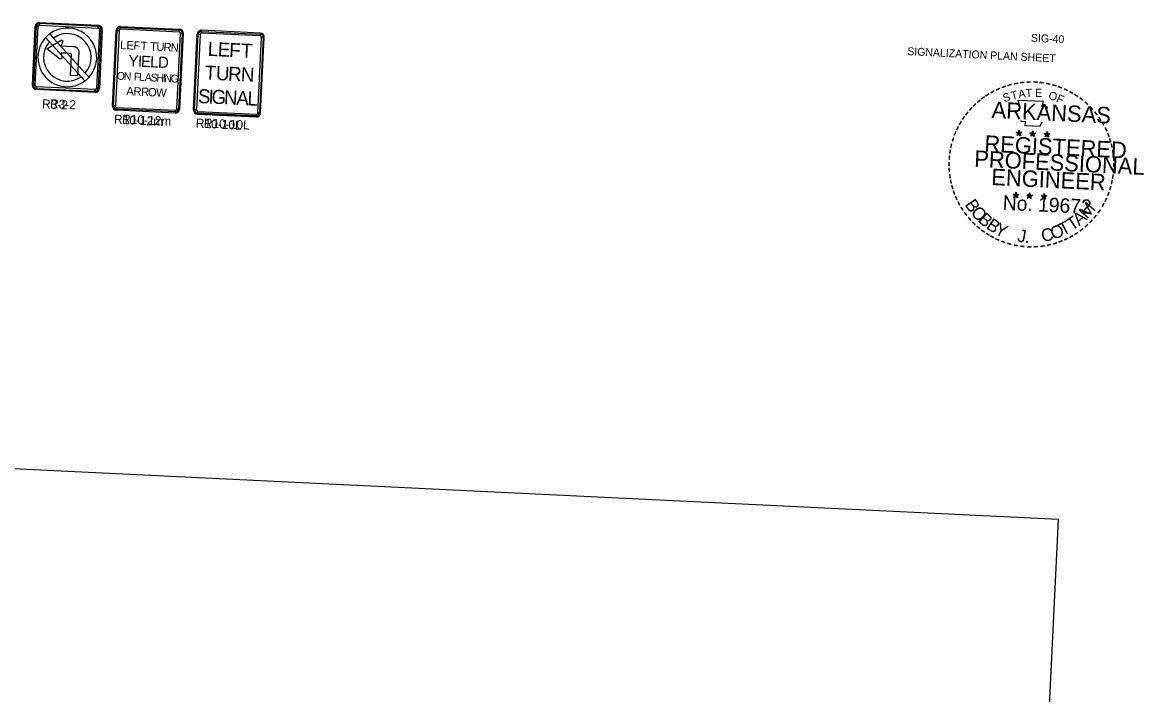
# Model space of a CAD drawing. Extents: x 662220 to 671027, y 641390 to 743815.
# Drawn here: x 662687 to 663189, y 642399 to 642699 of the extents above; entities that cross this region are included whole.
import ezdxf

# ---------------------------------------------------------------- set-up
doc = ezdxf.new("R2010")
doc.units = 0
for name, color, linetype in [('Default', 7, 'Continuous'), ('R_Border', 7, 'Continuous'), ('R_Proposed Road Annot', 7, 'Continuous'), ('TE_SG black legend_z_n', 7, 'Continuous'), ('TE_SG red shield_z_n', 7, 'Continuous'), ('TE_SG sign edge_z_n', 7, 'Continuous')]:
    doc.layers.add(name, color=color, linetype=linetype)

msp = doc.modelspace()

# ---------------------------------------------------------------- linework, layer by layer
at = {"layer": 'R_Border'}
for p, q in [((663131.65, 642650.37), (663132.9, 642649.9)), ((663131.65, 642650.37), (663132.56, 642650.16)), ((663131.65, 642650.37), (663132.49, 642649.88)), ((663132.06, 642648.86), (663132.9, 642649.9)), ((663132.06, 642648.86), (663132.56, 642649.73)), ((663132.97, 642651.24), (663132.77, 642650.32)), ((663132.9, 642649.9), (663132.97, 642651.24)), ((663134.19, 642650.25), (663132.9, 642649.9)), ((663133.63, 642648.78), (663132.9, 642649.9)), ((663132.97, 642651.24), (663133.1, 642650.32)), ((663134.19, 642650.25), (663133.14, 642650.12)), ((663133.63, 642648.78), (663133.18, 642649.87)), ((663134.19, 642650.25), (663133.43, 642649.91)), ((663137.76, 642650.08), (663139.01, 642649.61)), ((663137.76, 642650.08), (663138.67, 642649.87)), ((663137.76, 642650.08), (663138.6, 642649.59)), ((663139.08, 642650.94), (663138.88, 642650.03)), ((663139.01, 642649.61), (663139.08, 642650.94)), ((663140.3, 642649.95), (663139.01, 642649.61)), ((663139.08, 642650.94), (663139.21, 642650.02)), ((663140.3, 642649.95), (663139.25, 642649.82)), ((663140.3, 642649.95), (663139.54, 642649.61)), ((663144.21, 642649.72), (663145.46, 642649.25)), ((663144.21, 642649.72), (663145.12, 642649.51)), ((663144.21, 642649.72), (663145.05, 642649.23)), ((663145.53, 642650.59), (663145.33, 642649.67)), ((663145.46, 642649.25), (663145.53, 642650.59)), ((663145.53, 642650.59), (663145.66, 642649.66)), ((663132.06, 642648.86), (663132.88, 642649.61)), ((663133.63, 642648.78), (663132.88, 642649.6)), ((663138.17, 642648.56), (663139.01, 642649.61)), ((663138.17, 642648.56), (663138.67, 642649.43)), ((663138.17, 642648.56), (663138.99, 642649.32)), ((663139.74, 642648.48), (663138.99, 642649.3)), ((663139.74, 642648.48), (663139.01, 642649.61)), ((663139.74, 642648.48), (663139.29, 642649.57)), ((663144.62, 642648.2), (663145.46, 642649.25)), ((663144.62, 642648.2), (663145.12, 642649.07)), ((663144.62, 642648.2), (663145.44, 642648.96)), ((663146.19, 642648.13), (663145.44, 642648.95)), ((663146.75, 642649.59), (663145.46, 642649.25)), ((663146.19, 642648.13), (663145.46, 642649.25)), ((663146.75, 642649.59), (663145.7, 642649.47)), ((663146.19, 642648.13), (663145.74, 642649.21)), ((663146.75, 642649.59), (663145.99, 642649.26)), ((663130.29, 642622.67), (663131.54, 642622.2)), ((663130.29, 642622.67), (663131.2, 642622.46)), ((663130.29, 642622.67), (663131.13, 642622.18)), ((663130.7, 642621.15), (663131.54, 642622.2)), ((663130.7, 642621.15), (663131.2, 642622.02)), ((663130.7, 642621.15), (663131.52, 642621.91)), ((663131.61, 642623.54), (663131.41, 642622.62)), ((663132.27, 642621.08), (663131.52, 642621.9)), ((663131.54, 642622.2), (663131.61, 642623.54)), ((663132.83, 642622.55), (663131.54, 642622.2)), ((663132.27, 642621.08), (663131.54, 642622.2)), ((663131.61, 642623.54), (663131.74, 642622.61)), ((663132.83, 642622.55), (663131.78, 642622.42)), ((663132.27, 642621.08), (663131.82, 642622.17)), ((663132.83, 642622.55), (663132.07, 642622.21)), ((663136.39, 642622.37), (663137.65, 642621.91)), ((663136.39, 642622.37), (663137.31, 642622.16)), ((663136.39, 642622.37), (663137.24, 642621.89)), ((663136.8, 642620.86), (663137.65, 642621.91)), ((663136.8, 642620.86), (663137.31, 642621.73)), ((663136.8, 642620.86), (663137.63, 642621.61)), ((663137.71, 642623.24), (663137.52, 642622.33)), ((663138.37, 642620.78), (663137.63, 642621.6)), ((663137.65, 642621.91), (663137.71, 642623.24)), ((663138.94, 642622.25), (663137.65, 642621.91)), ((663138.37, 642620.78), (663137.65, 642621.91)), ((663137.71, 642623.24), (663137.85, 642622.32)), ((663138.94, 642622.25), (663137.88, 642622.12)), ((663138.37, 642620.78), (663137.92, 642621.87)), ((663138.94, 642622.25), (663138.17, 642621.91)), ((663142.85, 642622.02), (663144.11, 642621.55)), ((663142.85, 642622.02), (663143.77, 642621.81)), ((663142.85, 642622.02), (663143.7, 642621.53)), ((663143.27, 642620.51), (663144.11, 642621.55)), ((663143.27, 642620.51), (663143.77, 642621.38)), ((663143.27, 642620.51), (663144.09, 642621.26)), ((663144.17, 642622.89), (663143.98, 642621.98)), ((663144.84, 642620.43), (663144.09, 642621.25)), ((663144.11, 642621.55), (663144.17, 642622.89)), ((663145.4, 642621.9), (663144.11, 642621.55)), ((663144.84, 642620.43), (663144.11, 642621.55)), ((663144.17, 642622.89), (663144.31, 642621.97)), ((663145.4, 642621.9), (663144.34, 642621.77)), ((663144.84, 642620.43), (663144.39, 642621.52)), ((663145.4, 642621.9), (663144.63, 642621.56))]:
    msp.add_line(p, q, dxfattribs=at)
for points in [[(663132.49, 642664.55), (663133.32, 642661.48)], [(663145.17, 642660.55), (663145.74, 642661.57), (663143.23, 642661.6), (663143.88, 642664), (663132.49, 642664.55)], [(663133.85, 642655.6), (663133.84, 642655.28), (663135.9, 642655.11), (663135.61, 642653.39), (663142.45, 642653.06), (663143.28, 642654.98)], [(663132.97, 642651.24), (663133.63, 642648.78), (663131.65, 642650.37), (663134.19, 642650.25), (663132.06, 642648.86), (663132.97, 642651.24)], [(663139.08, 642650.94), (663139.74, 642648.48), (663137.76, 642650.08), (663140.3, 642649.95), (663138.17, 642648.56), (663139.08, 642650.94)], [(663145.53, 642650.59), (663146.19, 642648.13), (663144.21, 642649.72), (663146.75, 642649.59), (663144.62, 642648.2), (663145.53, 642650.59)], [(663131.61, 642623.54), (663132.27, 642621.08), (663130.29, 642622.67), (663132.83, 642622.55), (663130.7, 642621.15), (663131.61, 642623.54)], [(663137.71, 642623.24), (663138.37, 642620.78), (663136.39, 642622.37), (663138.94, 642622.25), (663136.8, 642620.86), (663137.71, 642623.24)], [(663144.17, 642622.89), (663144.84, 642620.43), (663142.85, 642622.02), (663145.4, 642621.9), (663143.27, 642620.51), (663144.17, 642622.89)]]:
    msp.add_lwpolyline(points, dxfattribs=at)
for centre, radius in [((663132.9, 642649.9), 0.631), ((663132.9, 642649.9), 0.529), ((663132.9, 642649.9), 0.424), ((663132.9, 642649.9), 0.363), ((663132.9, 642649.9), 0.274), ((663132.9, 642649.9), 0.181), ((663132.9, 642649.9), 0.109), ((663139.01, 642649.6), 0.631), ((663139.01, 642649.6), 0.529), ((663139.01, 642649.6), 0.424), ((663139.01, 642649.6), 0.363), ((663139.01, 642649.6), 0.274), ((663139.01, 642649.6), 0.181), ((663139.01, 642649.6), 0.109), ((663145.46, 642649.25), 0.631), ((663145.46, 642649.25), 0.529), ((663145.46, 642649.25), 0.424), ((663145.46, 642649.25), 0.363), ((663145.46, 642649.25), 0.274), ((663145.46, 642649.25), 0.181), ((663145.46, 642649.25), 0.109), ((663131.54, 642622.2), 0.631), ((663131.54, 642622.2), 0.529), ((663131.54, 642622.2), 0.424), ((663131.54, 642622.2), 0.363), ((663131.54, 642622.2), 0.274), ((663131.54, 642622.2), 0.181), ((663131.54, 642622.2), 0.109), ((663137.64, 642621.9), 0.631), ((663137.64, 642621.9), 0.529), ((663137.64, 642621.9), 0.424), ((663137.64, 642621.9), 0.363), ((663137.64, 642621.9), 0.274), ((663137.64, 642621.9), 0.181), ((663137.64, 642621.9), 0.109), ((663144.11, 642621.55), 0.631), ((663144.11, 642621.55), 0.529), ((663144.11, 642621.55), 0.424), ((663144.11, 642621.55), 0.363), ((663144.11, 642621.55), 0.274), ((663144.11, 642621.55), 0.181), ((663144.11, 642621.55), 0.109)]:
    msp.add_circle(centre, radius, dxfattribs=at)
at = {"layer": 'R_Proposed Road Annot'}
msp.add_lwpolyline([(662651.09, 642158.8), (663134.03, 642135.35), (663150.64, 642477.27), (662667.69, 642500.72)], close=True, dxfattribs=at)
at = {"layer": 'TE_SG black legend_z_n'}
for p, q in [((662693.66, 642697.58), (662694.44, 642697.54)), ((662695.09, 642698.14), (662695.13, 642698.92)), ((662721.35, 642697.64), (662721.31, 642696.86)), ((662721.91, 642696.21), (662722.69, 642696.17)), ((662729.87, 642695.82), (662730.65, 642695.79)), ((662731.3, 642696.38), (662731.34, 642697.16)), ((662757.56, 642695.89), (662757.52, 642695.11)), ((662767.51, 642694.62), (662767.55, 642695.4)), ((662758.11, 642694.45), (662758.89, 642694.41)), ((662766.07, 642694.07), (662766.85, 642694.03)), ((662793.76, 642694.13), (662793.73, 642693.35)), ((662794.32, 642692.69), (662795.1, 642692.66)), ((662707.1, 642685.59), (662704.58, 642685.71)), ((662704.79, 642688.97), (662707.26, 642688.85)), ((662708.87, 642685.51), (662707.1, 642685.59)), ((662707.26, 642688.85), (662710.27, 642688.7)), ((662708.95, 642685.5), (662708.87, 642685.51)), ((662709.01, 642675.65), (662709.46, 642684.85)), ((662710.27, 642688.7), (662710.43, 642688.69)), ((662712.65, 642686.09), (662712.13, 642675.49)), ((662712.13, 642675.49), (662709.01, 642675.65)), ((662693.17, 642671.32), (662692.38, 642671.36)), ((662693.72, 642669.89), (662693.76, 642670.67)), ((662721.41, 642669.95), (662720.63, 642669.99)), ((662719.98, 642669.4), (662719.94, 642668.62)), ((662729.01, 642662.08), (662728.23, 642662.11)), ((662729.56, 642660.64), (662729.6, 642661.42)), ((662755.82, 642660.15), (662755.78, 642659.37)), ((662757.26, 642660.7), (662756.48, 642660.74)), ((662765.22, 642660.32), (662764.44, 642660.35)), ((662765.77, 642658.88), (662765.81, 642659.66)), ((662792.03, 642658.39), (662791.99, 642657.61)), ((662793.46, 642658.95), (662792.68, 642658.98))]:
    msp.add_line(p, q, dxfattribs=at)
for points in [[(662693.66, 642697.58), (662692.38, 642671.36), (662693.17, 642671.32), (662694.44, 642697.54), (662693.66, 642697.58)], [(662721.35, 642697.64), (662695.13, 642698.92), (662695.09, 642698.14), (662721.31, 642696.86), (662721.35, 642697.64)], [(662721.41, 642669.95), (662722.69, 642696.17), (662721.91, 642696.21), (662720.63, 642669.99), (662721.41, 642669.95)], [(662730.65, 642695.79), (662729.01, 642662.08), (662728.23, 642662.11), (662729.87, 642695.82), (662730.65, 642695.79)], [(662757.52, 642695.11), (662731.3, 642696.38), (662731.34, 642697.16), (662757.56, 642695.89), (662757.52, 642695.11)], [(662793.73, 642693.35), (662767.51, 642694.62), (662767.55, 642695.4), (662793.76, 642694.13), (662793.73, 642693.35)], [(662756.48, 642660.74), (662758.11, 642694.45), (662758.89, 642694.41), (662757.26, 642660.7), (662756.48, 642660.74)], [(662766.85, 642694.03), (662765.22, 642660.32), (662764.44, 642660.35), (662766.07, 642694.07), (662766.85, 642694.03)], [(662792.68, 642658.98), (662794.32, 642692.69), (662795.1, 642692.66), (662793.46, 642658.95), (662792.68, 642658.98)], [(662693.72, 642669.89), (662719.94, 642668.62), (662719.98, 642669.4), (662693.76, 642670.67), (662693.72, 642669.89)], [(662729.6, 642661.42), (662755.82, 642660.15), (662755.78, 642659.37), (662729.56, 642660.64), (662729.6, 642661.42)], [(662765.81, 642659.66), (662792.03, 642658.39), (662791.99, 642657.61), (662765.77, 642658.88), (662765.81, 642659.66)]]:
    msp.add_lwpolyline(points, close=True, dxfattribs=at)
for points in [[(662704.58, 642685.71), (662705.08, 642683.85), (662705.1, 642683.77), (662705.11, 642683.69), (662705.1, 642683.61), (662705.09, 642683.53), (662705.06, 642683.45), (662705.02, 642683.38), (662704.98, 642683.31), (662704.93, 642683.25), (662704.86, 642683.19), (662704.8, 642683.15), (662704.72, 642683.11), (662704.65, 642683.08), (662704.57, 642683.07), (662704.49, 642683.06), (662704.41, 642683.07), (662704.32, 642683.09), (662704.25, 642683.11), (662704.17, 642683.15), (662704.1, 642683.19), (662698.34, 642687.58), (662704.5, 642691.38), (662704.57, 642691.42), (662704.65, 642691.46), (662704.73, 642691.47), (662704.81, 642691.48), (662704.89, 642691.48), (662704.97, 642691.47), (662705.05, 642691.44), (662705.13, 642691.4), (662705.2, 642691.36), (662705.26, 642691.31), (662705.31, 642691.25), (662705.36, 642691.18), (662705.4, 642691.11), (662705.43, 642691.04), (662705.45, 642690.96), (662705.46, 642690.88), (662705.45, 642690.8), (662705.44, 642690.72), (662705.41, 642690.64), (662704.79, 642688.97)], [(662709.46, 642684.85), (662709.45, 642684.94), (662709.45, 642685.02), (662709.43, 642685.09), (662709.39, 642685.17), (662709.35, 642685.24), (662709.3, 642685.3), (662709.24, 642685.36), (662709.18, 642685.41), (662709.1, 642685.45), (662709.03, 642685.47), (662708.95, 642685.5)], [(662710.43, 642688.69), (662710.6, 642688.67), (662710.76, 642688.64), (662710.91, 642688.59), (662711.06, 642688.53), (662711.22, 642688.47), (662711.36, 642688.4), (662711.5, 642688.31), (662711.63, 642688.22), (662711.76, 642688.12), (662711.88, 642688.01), (662712, 642687.89), (662712.1, 642687.76), (662712.2, 642687.64), (662712.29, 642687.5), (662712.37, 642687.36), (662712.44, 642687.21), (662712.5, 642687.05), (662712.55, 642686.9), (662712.59, 642686.74), (662712.62, 642686.58), (662712.64, 642686.42), (662712.65, 642686.25), (662712.65, 642686.09)]]:
    msp.add_lwpolyline(points, dxfattribs=at)
for centre, radius, start, end in [((662695.06, 642697.51), 1.41, 87.2201, 177.2198), ((662695.06, 642697.51), 0.625, 87.2201, 177.2198), ((662721.28, 642696.24), 0.625, 357.2199, 87.2201), ((662721.28, 642696.24), 1.41, 357.2199, 87.2201), ((662731.27, 642695.76), 1.41, 87.2201, 177.2198), ((662731.27, 642695.76), 0.625, 87.2201, 177.2198), ((662757.49, 642694.48), 0.625, 357.2199, 87.2201), ((662757.49, 642694.48), 1.41, 357.2199, 87.2201), ((662767.48, 642694), 1.41, 87.2201, 177.2198), ((662767.48, 642694), 0.625, 87.2201, 177.2198), ((662793.7, 642692.72), 0.625, 357.2199, 87.2201), ((662793.7, 642692.72), 1.41, 357.2199, 87.2201), ((662693.79, 642671.29), 1.41, 177.2198, 267.22), ((662693.79, 642671.29), 0.625, 177.2198, 267.22), ((662720.01, 642670.02), 1.41, 267.22, 357.2202), ((662720.01, 642670.02), 0.625, 267.22, 357.2202), ((662729.63, 642662.04), 1.41, 177.2198, 267.22), ((662729.63, 642662.04), 0.625, 177.2198, 267.22), ((662755.85, 642660.77), 1.41, 267.22, 357.2202), ((662755.85, 642660.77), 0.625, 267.22, 357.2202), ((662765.84, 642660.29), 1.41, 177.2198, 267.22), ((662765.84, 642660.29), 0.625, 177.2198, 267.22), ((662792.06, 642659.01), 1.41, 267.22, 357.2202), ((662792.06, 642659.01), 0.625, 267.22, 357.2202)]:
    msp.add_arc(centre, radius, start, end, dxfattribs=at)
at = {"layer": 'TE_SG red shield_z_n'}
for p, q in [((662697.83, 642692.6), (662699.52, 642690.74)), ((662699.52, 642690.74), (662697.83, 642692.6)), ((662713.7, 642675.11), (662699.52, 642690.74)), ((662699.68, 642694.28), (662701.37, 642692.42)), ((662699.68, 642694.28), (662701.37, 642692.42)), ((662701.37, 642692.42), (662715.55, 642676.79)), ((662713.7, 642675.11), (662715.39, 642673.25)), ((662715.39, 642673.25), (662713.7, 642675.11)), ((662715.55, 642676.79), (662717.24, 642674.93)), ((662715.55, 642676.79), (662717.24, 642674.93))]:
    msp.add_line(p, q, dxfattribs=at)
for radius, start, end in [(13.13, 357.2199, 126.7549), (13.13, 137.6848, 306.7548), (10.63, 138.9761, 305.4638), (13.13, 126.7549, 137.6848), (10.63, 318.9764, 125.4636), (13.13, 326.9969, 357.2202), (13.13, 306.7548, 317.685), (13.13, 317.685, 326.9969)]:
    msp.add_arc((662707.54, 642683.77), radius, start, end, dxfattribs=at)
at = {"layer": 'TE_SG sign edge_z_n'}
for p, q in [((662691.92, 642671.39), (662693.19, 642697.6)), ((662695.15, 642699.39), (662721.37, 642698.11)), ((662723.15, 642696.15), (662721.88, 642669.93)), ((662727.76, 642662.14), (662729.4, 642695.85)), ((662731.36, 642697.63), (662757.58, 642696.35)), ((662793.79, 642694.6), (662767.57, 642695.87)), ((662793.79, 642694.6), (662767.57, 642695.87)), ((662759.36, 642694.39), (662757.72, 642660.68)), ((662763.97, 642660.38), (662765.6, 642694.09)), ((662765.6, 642694.09), (662763.97, 642660.38)), ((662793.93, 642658.92), (662795.57, 642692.63)), ((662793.93, 642658.92), (662795.57, 642692.63)), ((662719.92, 642668.15), (662693.7, 642669.42)), ((662755.76, 642658.9), (662729.54, 642660.17)), ((662791.97, 642657.14), (662765.75, 642658.41)), ((662765.75, 642658.41), (662791.97, 642657.14))]:
    msp.add_line(p, q, dxfattribs=at)
for centre, start, end in [((662695.06, 642697.51), 87.2199, 177.2199), ((662721.28, 642696.24), 357.2199, 87.2199), ((662731.27, 642695.76), 87.2199, 177.2199), ((662757.49, 642694.48), 357.2199, 87.2199), ((662767.48, 642694), 87.2199, 177.2199), ((662793.7, 642692.72), 357.2199, 87.2199), ((662693.79, 642671.29), 177.2199, 267.2199), ((662720.01, 642670.02), 267.2199, 357.2199), ((662729.63, 642662.04), 177.2199, 267.2199), ((662755.85, 642660.77), 267.2199, 357.2199), ((662765.84, 642660.29), 177.2199, 267.2199), ((662792.06, 642659.01), 267.2199, 357.2199)]:
    msp.add_arc(centre, 1.88, start, end, dxfattribs=at)

# ---------------------------------------------------------------- texts
at = {"layer": 'Default'}
for s, p in [('R3-2', (662696.14, 642661.04)), ('R3-2', (662699.73, 642661.11)), ('R10-12m', (662728.32, 642654.2)), ('R10-12m', (662731.91, 642654.27)), ('R10-10L', (662764.87, 642652.42)), ('R10-10L', (662768.46, 642652.5))]:
    msp.add_text(s, height=4, rotation=357.2199, dxfattribs=at).set_placement(p)
at = {"layer": 'R_Border'}
for s, height, rotation, p in [('SIG-40', 3.517, 357.2199, (663138.22, 642690.81)), ('SIGNALIZATION PLAN SHEET', 3.5172, 357.2199, (663082.93, 642684.8)), ('-', 5.86, 26.0102, (663123.37, 642666.98)), ('-', 5.86, 21.5255, (663125.74, 642668.03)), ('-', 5.86, 16.3944, (663128.11, 642668.9)), ('-', 5.86, 10.8485, (663130.89, 642669.64)), ('-', 5.86, 7.4377, (663133.4, 642670.12)), ('T', 3.66, 3.2411, (663136.01, 642665.94)), ('-', 5.86, 3.1152, (663136.09, 642670.39)), ('-', 5.86, 357.4046, (663138.92, 642670.52)), ('E', 3.66, 358.0507, (663140.08, 642666.15)), ('-', 5.86, 354.9614, (663141.57, 642670.34)), ('-', 5.86, 349.3801, (663144.28, 642670)), ('-', 5.86, 344.4232, (663146.89, 642669.46)), ('-', 5.86, 339.5545, (663149.18, 642668.78)), ('-', 5.86, 335.0734, (663151.83, 642667.83)), ('-', 5.86, 40.1806, (663115.47, 642661.64)), ('-', 5.86, 36.169, (663117.12, 642663.09)), ('-', 5.86, 33.4501, (663118.93, 642664.39)), ('-', 5.86, 31.2819, (663121.12, 642665.73)), ('S', 3.66, 18.8123, (663126.41, 642663.67)), ('T', 3.66, 13.6219, (663129.81, 642664.71)), ('A', 3.66, 8.4315, (663132.88, 642665.49)), ('O', 3.66, 347.6698, (663145.91, 642665.09)), ('F', 3.66, 337.289, (663149.36, 642664.09)), ('-', 5.86, 331.3394, (663154.09, 642666.73)), ('-', 5.86, 326.8592, (663156.16, 642665.59)), ('-', 5.86, 323.081, (663158.45, 642664.16)), ('-', 5.86, 47.8325, (663112.18, 642658.27)), ('-', 5.86, 45.6414, (663113.74, 642659.97)), ('ARKANSAS', 7.325, 357.2183, (663120.57, 642656.74)), ('-', 5.86, 317.748, (663160.6, 642662.49)), ('-', 5.86, 312.7969, (663162.71, 642660.6)), ('-', 5.86, 307.0981, (663164.69, 642658.48)), ('-', 5.86, 60.0897, (663108.03, 642652.21)), ('-', 5.86, 55.289, (663109.29, 642654.4)), ('-', 5.86, 51.4508, (663110.57, 642656.27)), ('-', 5.86, 303.8705, (663166.51, 642656.19)), ('-', 5.13, 300.8936, (663168.18, 642654.02)), ('-', 5.86, 69.6128, (663106.06, 642647.75)), ('-', 5.86, 64.9926, (663106.98, 642650.02)), ('-', 5.86, 296.8867, (663169.24, 642651.75)), ('-', 5.86, 291.8811, (663170.32, 642649.45)), ('-', 5.86, 78.4196, (663104.61, 642642.59)), ('-', 5.86, 72.6793, (663105.22, 642645.17)), ('REGISTERED', 7.325, 357.2183, (663117.35, 642641.68)), ('-', 5.86, 287.7912, (663171.16, 642647.29)), ('-', 5.86, 282.3416, (663171.91, 642645.13)), ('-', 5.86, 86.2806, (663103.99, 642637.51)), ('-', 5.86, 82.4047, (663104.21, 642640.07)), ('PROFESSIONAL', 7.3249, 357.2183, (663112.81, 642634.92)), ('-', 5.86, 277.7677, (663172.51, 642642.38)), ('-', 5.86, 91.4142, (663103.99, 642634.86)), ('-', 5.86, 273.8145, (663172.97, 642639.54)), ('-', 5.86, 271.5484, (663173.06, 642636.89)), ('-', 5.86, 96.1663, (663104.13, 642632.4)), ('-', 5.86, 98.9333, (663104.5, 642629.7)), ('ENGINEER', 7.325, 357.2183, (663120.43, 642626.76)), ('-', 5.86, 260.7355, (663172.88, 642632.14)), ('-', 5.86, 267.159, (663173.07, 642634.57)), ('-', 5.86, 102.6762, (663104.98, 642627.49)), ('-', 5.86, 106.3058, (663105.66, 642625.15)), ('-', 5.86, 252.9809, (663171.98, 642627.3)), ('-', 5.86, 258.2136, (663172.5, 642629.76)), ('-', 5.86, 111.2827, (663106.48, 642622.92)), ('-', 5.86, 112.9472, (663107.49, 642620.61)), ('B', 5.64, 304.0732, (663108.48, 642618.04)), ('No. 19672', 6.435, 357.2183, (663125.59, 642615.69)), ('-', 5.86, 245.107, (663170.26, 642622.28)), ('-', 5.86, 250.0864, (663171.19, 642624.7)), ('-', 5.86, 117.6655, (663108.69, 642618.4)), ('-', 5.86, 123.1118, (663110.06, 642616.28)), ('-', 5.86, 127.9365, (663111.66, 642614.17)), ('O', 5.64, 312.1834, (663111.07, 642614.2)), ('M', 5.64, 48.2474, (663163.35, 642611.28)), ('-', 5.86, 236.2896, (663167.61, 642617.34)), ('-', 5.86, 241.838, (663169.19, 642620.02)), ('-', 5.86, 131.4421, (663113.45, 642612.09)), ('-', 5.86, 136.1522, (663115.29, 642610.3)), ('B', 5.64, 317.964, (663114.26, 642610.72)), ('B', 5.64, 326.0742, (663117.91, 642607.6)), ('Y', 5.64, 334.1844, (663121.63, 642605.19)), ('T', 5.64, 27.3561, (663152.53, 642603.89)), ('T', 5.64, 34.2369, (663156.58, 642606.08)), ('A', 5.64, 40.1373, (663159.81, 642608.27)), ('-', 5.86, 228.4721, (663164.35, 642613.03)), ('-', 5.86, 231.0636, (663166.02, 642615.02)), ('-', 5.86, 141.8647, (663117.25, 642608.71)), ('-', 5.86, 145.3081, (663119.24, 642607.26)), ('-', 5.86, 148.7887, (663121.3, 642605.96)), ('J', 5.64, 350.5606, (663131.98, 642601.52)), ('C', 5.64, 11.1357, (663143.45, 642601.24)), ('O', 5.64, 19.2459, (663148.13, 642602.26)), ('-', 5.86, 212.9547, (663158.41, 642607.65)), ('-', 5.86, 218.3034, (663160.5, 642609.28)), ('-', 5.86, 222.9837, (663162.5, 642611.05)), ('-', 5.86, 151.8185, (663123.16, 642604.97)), ('-', 5.86, 155.7795, (663125.4, 642603.93)), ('-', 5.86, 160.0166, (663127.88, 642603.03)), ('-', 5.86, 164.7738, (663130.46, 642602.3)), ('-', 5.86, 170.3338, (663133.27, 642601.76)), ('-', 5.86, 173.7366, (663135.99, 642601.43)), ('.', 5.64, 350.5606, (663135.41, 642601.07)), ('-', 5.86, 183.035, (663141.69, 642601.51)), ('-', 5.86, 188.5041, (663144.41, 642601.86)), ('-', 5.86, 192.6926, (663147.11, 642602.46)), ('-', 5.86, 197.9368, (663149.63, 642603.22)), ('-', 5.86, 201.4699, (663151.94, 642604.11)), ('-', 5.86, 204.5752, (663154.28, 642605.17)), ('-', 5.86, 209.4674, (663156.38, 642606.33)), ('-', 5.86, 178.6215, (663138.92, 642601.35))]:
    msp.add_text(s, height=height, rotation=rotation, dxfattribs=at).set_placement(p)
at = {"layer": 'TE_SG black legend_z_n'}
for s, height, p in [('L', 3.75, (662731.05, 642687.52)), ('E', 3.75, (662733.85, 642687.39)), ('F', 3.75, (662737.05, 642687.23)), ('T', 3.75, (662740.22, 642687.08)), ('T', 3.75, (662744.46, 642686.87)), ('U', 3.75, (662747.26, 642686.74)), ('R', 3.75, (662750.46, 642686.58)), ('N', 3.75, (662753.66, 642686.42)), ('L', 6.25, (662770.18, 642684.48)), ('E', 6.25, (662774.65, 642684.26)), ('F', 6.25, (662779.75, 642684.01)), ('T', 6.25, (662785.02, 642683.76)), ('Y', 5, (662734.74, 642679.83)), ('I', 5, (662739.02, 642679.63)), ('E', 5, (662740.35, 642679.56)), ('L', 5, (662744.44, 642679.36)), ('D', 5, (662747.97, 642679.19)), ('T', 6.25, (662768.84, 642673.91)), ('U', 6.25, (662773.85, 642673.66)), ('O', 3.5, (662729.59, 642673.83)), ('N', 3.5, (662732.69, 642673.68)), ('F', 3.5, (662737.17, 642673.46)), ('L', 3.5, (662739.51, 642673.35)), ('A', 3.5, (662742.11, 642673.22)), ('S', 3.5, (662744.72, 642673.09)), ('H', 3.5, (662747.3, 642672.97)), ('I', 3.5, (662750.14, 642672.83)), ('N', 3.5, (662750.8, 642672.8)), ('G', 3.5, (662753.68, 642672.66)), ('R', 6.25, (662779.28, 642673.4)), ('N', 6.25, (662784.98, 642673.12)), ('A', 3.75, (662733.84, 642666.91)), ('R', 3.75, (662737.03, 642666.75)), ('R', 3.75, (662740.42, 642666.59)), ('O', 3.75, (662743.53, 642666.44)), ('W', 3.75, (662747.12, 642666.26)), ('S', 6.25, (662765.8, 642663.42)), ('I', 6.25, (662770.53, 642663.19)), ('G', 6.25, (662771.85, 642663.12)), ('N', 6.25, (662777.45, 642662.85)), ('A', 6.25, (662782.97, 642662.58)), ('L', 6.25, (662787.93, 642662.34))]:
    msp.add_text(s, height=height, rotation=357.2199, dxfattribs=at).set_placement(p)

doc.saveas('drawing.dxf')
